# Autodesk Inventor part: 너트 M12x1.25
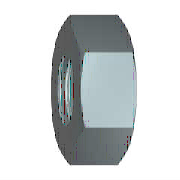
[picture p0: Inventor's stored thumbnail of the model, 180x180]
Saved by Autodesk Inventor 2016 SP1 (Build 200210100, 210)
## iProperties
IsCustomPart: 1
Created: 2012-02
Part Number: 너트 M12x1.25
Material: 강철, 연강
Description: 6각 너트
Document SubType Name: Modeling
Standard: KS B 1012
Designer: mduedu
Standards Organization: KS
Language: ko-KR
Size Designation: M12x1.25
Categories: <MemberInstance><Categories><Category DisplayName="조임쇠" InternalName="e4da775c-781d-43d5-af7c-5136215cf5a6" Mnemonic="FSTN"><Category DisplayName="너트" InternalN
Density: 1 g/cm^3
Appearance: 강철
Author: mduedu
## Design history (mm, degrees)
sketch "스케치1"
  geometry: L1 (-10.97, 0)-(-5.485, 9.5); L2 (-5.485, 9.5)-(5.485, 9.5); L3 (5.485, 9.5)-(10.97, 0); L4 (10.97, 0)-(5.485, -9.5); L5 (5.485, -9.5)-(-5.485, -9.5); L6 (-5.485, -9.5)-(-10.97, 0); 2 further points
  constraints: 12 end point, 1 coincident, 1 horizontal, 11 other
  dimensions: "d0" = 21.93931 distance of L3.end L1.start (= 1.1547 x SW)
extrude "본체" new body sketch "스케치1" distance "d1" = 10 (= KOH); taper "d2" = 0 deg
sketch "스케치2"
  geometry: L1 (0, 5.485)-(0, 10.97) reference; L2 (0, 10.97)-(10, 10.97) reference; L3 (10, 5.485)-(10, 10.97) reference; L4 (-2, 0)-(12, 0) reference; L5 (0.849, 10.97)-(0, 9.5); L6 (9.151, 10.97)-(10, 9.5)
  constraints: 4 end point, 4 point on line
  dimensions: "d3" = 30 deg angle of L1 L5 (= ANG1); "d4" = 30 deg angle of L3 L6 (= ANG2); "d5" = 19 diameter of L5.end L4 (= SW0); "d6" = 19 diameter of L6.end L4 (= SW01)
revolve "모따기1" sketch "스케치2" stored, may be unused: angle "d7" = 90 deg
sketch "스케치3"
  geometry: A1 r 9.5 centre (0, 0) between (-4.75, -8.227) and (4.75, -8.227) reference; 1 further point
  constraints: 1 coincident
hole "스레드" sketch "스케치3" at (0, 0) diameter "d25" = 10.647; stored, may be unused: countersink angle "d29" = 82 deg, drill point angle "d31" = 118 deg; dims "d26" = 6, "d27" = 4, "d28" = 2, "d30" = 8
workaxis "Work Axis1"
workplane "Work Plane1"
body "Solid1"
chamfer "모따기2" distance "d8" = 0.67658 (= -0.5 x GD1 + 0.5 x NND); stored, may be unused: angle "d9" = 30 deg, second distance "d40" = 0.67658 (= -0.5 x GD1 + 0.5 x NND)
chamfer "모따기3" distance "d10" = 0.67658 (= -0.5 x GD1 + 0.5 x NND); stored, may be unused: angle "d11" = 30 deg, second distance "d41" = 0.67658 (= -0.5 x GD1 + 0.5 x NND)
other parameters: "ANG1" = 30 deg [user parameter; used in 1 equation term], "ANG2" = 30 deg [user parameter; used in 1 equation term], "NND" = 12 [user parameter; used in 4 equation terms], "KOH" = 10 [user parameter; used in 1 equation term], "SW" = 19 [user parameter; used in 4 equation terms], "SW0" = 19 (= SW) [user parameter; used in 1 equation term], "SW01" = 19 (= SW) [user parameter; used in 1 equation term], "GD1" = 10.64684 (computed from THREADDIA, PTC, TOA) [user parameter; used in 4 equation terms], "d13" = 0, "d14" = 0, "d39" = 0, "d42" = 0, "GUL" = 0.67658 (= 0.541266 x PTC) [user parameter], "TPU" = 8 (computed from PTC) [user parameter], "THREADDIA" = 12 [user parameter; used in 1 equation term], "TOA" = 30 deg [user parameter; used in 1 equation term], "PTC" = 1.25 [user parameter; used in 4 equation terms], "E0" = 21.945 (= 1.155 x SW) [user parameter], "GAL" = 0.67658 (= 0.541266 x PTC) [user parameter]
